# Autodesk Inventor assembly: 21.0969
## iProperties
Created: 2012-01
Part Number: 21.0969
Document SubType Name: Assembly
Designer: Administrator
Description: ANGLE 25 GD-Z
Stock Number: 21.0969 ANGLE 25 GD-Z
Vendor: S
Author: Administrator
